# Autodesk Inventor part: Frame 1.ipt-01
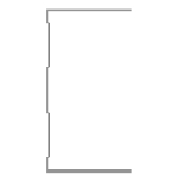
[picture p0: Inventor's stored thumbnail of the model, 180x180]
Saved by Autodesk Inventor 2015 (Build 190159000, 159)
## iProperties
Created: 2015-04
Part Number: Frame 1.ipt-01
Material: Aluminum 6061
Description: Kévin Novo
Document SubType Name: Modeling
Standard: Kevin
Designer: suporte
Standards Organization: Kevin
Language: en-US
Size Designation: (Unnamed 1)
Categories: <MemberInstance><Categories><Category DisplayName="Structural Shapes" InternalName="089c4875-fa83-4c05-b084-43b9cc11f5ed" Mnemonic="GRDR"><CategoryParameter Dis
Density: 2.7 g/cm^3
Appearance: Aluminum - Flat
_CCFamilyMember: 1
_CCFamilyDisplayName: Kévin - Kévin Novo
_FrameMemberDoc: Frame Member File
_Version: 15.0.0
_GetPNFromCC: 1
IsCustomPart: 1
Author: suporte
G_L: 1150,000 mm
G_W: 50,000 mm
G_H: 75,000 mm
+E893309B-5B4C-4D46-95ED-955E91FBA60A+CUTDETAIL1: Cut
+6052804E-6593-4938-B763-12C79B00D91D+CUTDETAIL2: Cut
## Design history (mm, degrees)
node "Start Plane"
node "End Plane"
sketch "Sketch"
  geometry: L1 (24.7, 37.5)-(24.7, 36.9); L2 (24.7, 36.9)-(-24.7, 36.9); L3 (-24.7, -36.9)-(24.7, -36.9); L4 (24.7, -36.9)-(24.7, -37.5); L5 (24.7, -37.5)-(-25.3, -37.5); L6 (-25.3, 37.5)-(24.7, 37.5); L7 (-24.7, 36.9)-(-24.7, 31.9); L8 (-24.7, 31.9)-(-23.3, 30.5); L9 (-23.3, 30.5)-(-23.3, 10.934); L10 (-23.3, 10.934)-(-24.7, 9.534); L11 (-24.7, 9.534)-(-24.7, -9.534); L12 (-24.7, -9.534)-(-23.3, -10.934); L13 (-23.3, -10.934)-(-23.3, -30.5); L14 (-23.3, -30.5)-(-24.7, -31.9); L15 (-24.7, -31.9)-(-24.7, -36.9); L16 (-25.3, -37.5)-(-25.3, -31.651); L17 (-25.3, -31.651)-(-23.9, -30.251); L18 (-23.9, -30.251)-(-23.9, -11.183); L19 (-23.9, -11.183)-(-25.3, -9.783); L20 (-25.3, -9.783)-(-25.3, 9.783); L21 (-25.3, 9.783)-(-23.9, 11.183); L22 (-23.9, 11.183)-(-23.9, 30.251); L23 (-23.9, 30.251)-(-25.3, 31.651); L24 (-25.3, 31.651)-(-25.3, 37.5); L25 (-25.3, 0)-(30.37, 0); 3 further points
  constraints: 50 end point, 10 point on line, 9 parallel, 5 perpendicular, 4 equal length, 3 midpoint, 3 vertical, 2 vertical alignment, 1 collinear, 1 horizontal, 1 horizontal alignment
  dimensions: "d3" = 0.6 distance of L1.start L1.end (= d6); "d5" = 75 distance between parallel lines of L5 L6; "d6" = 0.6 distance between parallel lines of L24 L7 (= d8); "d7" = 0.6 distance between parallel lines of L8 L23 (= d8); "d8" = 0.6 distance between parallel lines of L22 L9 (= d12); "Espessura" = 0.6 distance between parallel lines of L17 L14; "d10" = 0.6 distance between parallel lines of L13 L18 (= Espessura); "d11" = 0.6 distance between parallel lines of L12 L19 (= Espessura); "d12" = 0.6 distance between parallel lines of L21 L10 (= d11); "d13" = 5 distance of L2.end L7.end; "d15" = 135 deg angle of L9 L8; "d16" = 2 distance between parallel lines of L24 L9; "d17" = 50 distance of L6.start L1.start
extrude "Body" join sketch "Sketch" stored distance "d24" = 0.13; taper "d25" = 0 deg
node "Driven Length"
  sketch "Sketch10"
    geometry: L1 (0, 0)-(10, 0) reference
    constraints: 2 end point, 1 horizontal
  workplane "Work Plane7"
  sketch "Sketch11"
    geometry: L1 (-2, 12.5)-(12, 12.5) reference; L2 (-2, 1162.5)-(12, 1162.5) reference
    dimensions: "d27" = 1150 distance between parallel lines of L1 L2 (derived)
workplane "Work Plane8"
split "Split1"
workplane "Work Plane9"
split "Split2"
body "Solid1"
other parameters: "G_OFFSET_START" = -12.5 [user parameter; used in 1 equation term], "G_OFFSET_END" = -37.5 [user parameter; used in 1 equation term], "d22" = 12.5 (= -G_OFFSET_START), "d23" = 1162.5 (= tamanho + G_OFFSET_END), "G_L" = 1150 (= d27) [user parameter], "d34" = 90 deg
